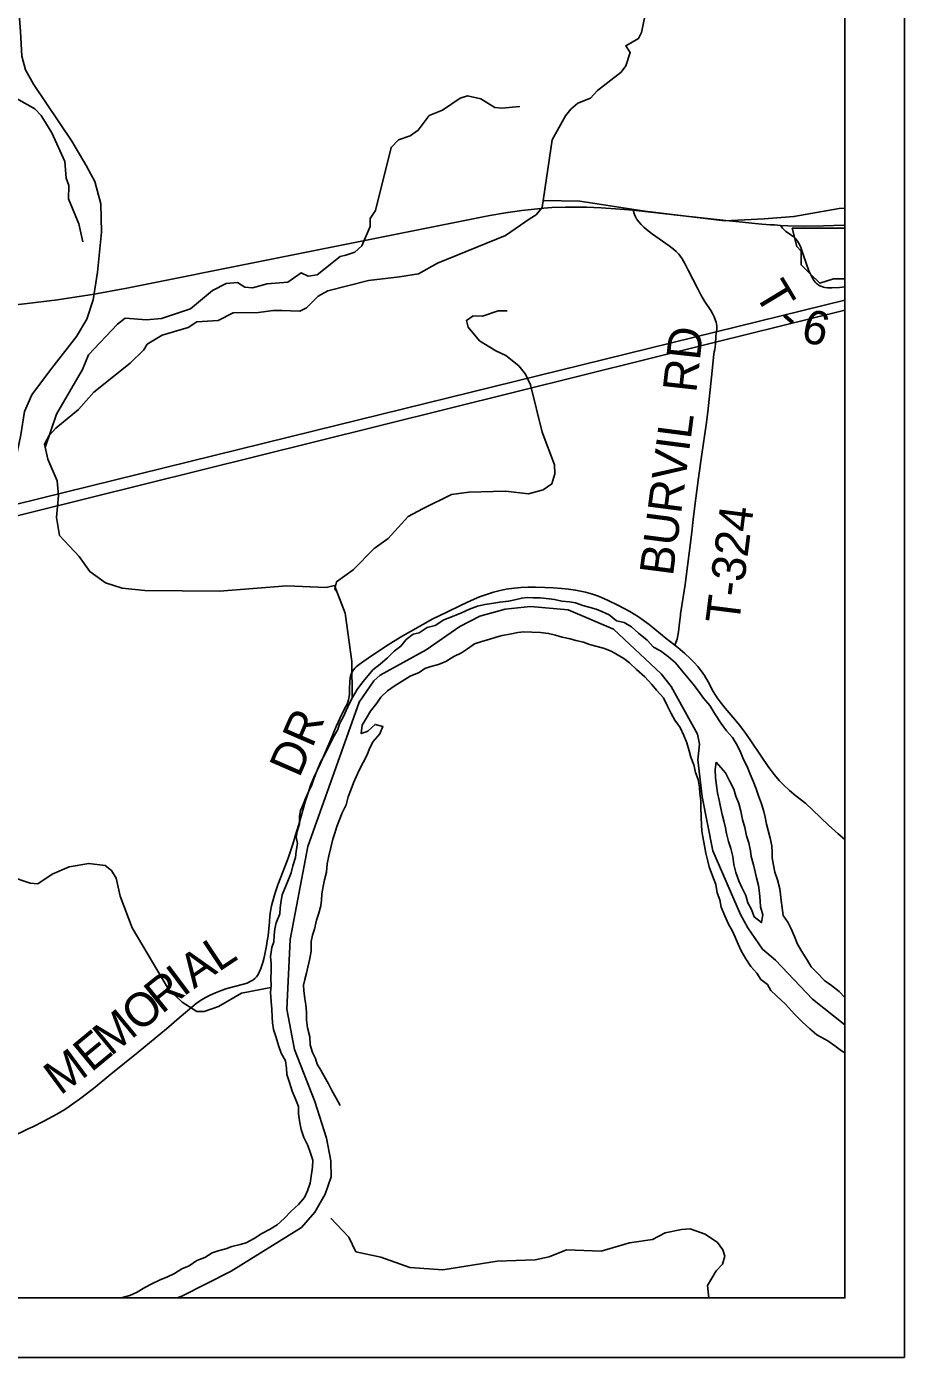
# Model space of a CAD drawing. Extents: x 0 to 34, y 0 to 22.
# Drawn here: x 7.523 to 9, y 14 to 16.238 of the extents above; entities that cross this region are included whole.
import ezdxf

# ---------------------------------------------------------------- set-up
doc = ezdxf.new("R2010")
doc.units = 0
for name, color, linetype in [('GM_X_Corporation', 7, 'Continuous'), ('GM_X_County_Road', 7, 'Continuous'), ('GM_X_County_Road_Text', 7, 'Continuous'), ('GM_X_Major_River', 7, 'Continuous'), ('GM_X_Minor_Lake', 7, 'Continuous'), ('GM_X_Minor_River', 7, 'Continuous'), ('GM_X_Rail_Line', 7, 'Continuous'), ('GM_X_State_Route', 7, 'Continuous'), ('GM_X_Township_Road', 7, 'Continuous'), ('GM_X_Township_Road_Text', 7, 'Continuous'), ('SH_Data', 7, 'Continuous')]:
    doc.layers.add(name, color=color, linetype=linetype)

msp = doc.modelspace()

# ---------------------------------------------------------------- linework, layer by layer
at = {"layer": 'GM_X_Corporation'}
for points in [[(2.1, 16.4477), (2.1, 14.1), (8.9, 14.1), (8.9, 16.2485)], [(7.4614, 14.1), (7.7766, 14.1), (7.7846, 14.103), (7.8675, 14.1449), (7.9856, 14.2182), (8.0084, 14.2441), (8.0256, 14.2746), (8.0359, 14.3039), (8.0349, 14.3304), (8.0278, 14.3687), (8.0084, 14.4303), (7.974, 14.5177), (7.9614, 14.5855), (7.9665, 14.7027), (7.9962, 14.8591), (8.083, 15.1017), (8.1073, 15.1379), (8.1182, 15.1474), (8.1953, 15.1901), (8.2521, 15.2295), (8.2856, 15.2464), (8.3286, 15.2585), (8.3709, 15.2629), (8.4345, 15.2573), (8.5104, 15.2245), (8.5908, 15.1499), (8.6079, 15.1281), (8.6517, 15.0484), (8.6556, 15.0313), (8.6528, 15.0048), (8.6598, 14.943), (8.6779, 14.8521), (8.7242, 14.7451), (8.7368, 14.7224), (8.7613, 14.6866), (8.783, 14.6678), (8.8452, 14.6022), (8.9, 14.5591), (8.9, 16.2485)]]:
    msp.add_lwpolyline(points, dxfattribs=at)
at = {"layer": 'GM_X_County_Road'}
for points in [[(7.6121, 14.4341), (7.6265, 14.4448), (7.6387, 14.4544), (7.6649, 14.4763), (7.7108, 14.5134), (7.7589, 14.5527), (7.7801, 14.5709), (7.8012, 14.5892), (7.8085, 14.595), (7.8161, 14.6003), (7.8241, 14.6051), (7.8324, 14.6094), (7.8409, 14.6132), (7.8495, 14.6166), (7.8584, 14.6196), (7.8733, 14.6239), (7.8884, 14.6276), (7.8943, 14.6295), (7.8971, 14.6308), (7.9008, 14.6326), (7.9039, 14.6345), (7.9073, 14.6371), (7.9101, 14.6399), (7.9129, 14.6441), (7.9147, 14.6477), (7.9175, 14.6543), (7.9193, 14.6593), (7.9209, 14.6643), (7.9229, 14.6724), (7.9268, 14.6923), (7.9283, 14.7008), (7.9297, 14.7091), (7.9317, 14.7325), (7.9328, 14.7426), (7.9339, 14.7507), (7.9355, 14.7596), (7.9399, 14.7755), (7.9425, 14.7844), (7.9461, 14.7947), (7.951, 14.8076), (7.9632, 14.8397), (7.9712, 14.8632), (7.9753, 14.8766), (7.9811, 14.8964), (7.9919, 14.9345), (7.997, 14.9496), (8.0009, 14.9619), (8.0077, 14.978), (8.0154, 14.9939), (8.0353, 15.0391), (8.0443, 15.061), (8.0503, 15.0746), (8.0583, 15.0908), (8.0625, 15.0985), (8.064, 15.1021), (8.0651, 15.1059), (8.0657, 15.1089), (8.0665, 15.115), (8.0667, 15.1181), (8.0668, 15.1242), (8.0673, 15.1367), (8.0678, 15.1428), (8.0684, 15.1459), (8.0693, 15.1489), (8.0705, 15.1517), (8.072, 15.1544), (8.0738, 15.1569), (8.0758, 15.1593), (8.078, 15.1614), (8.0828, 15.1654), (8.0905, 15.1707), (8.0981, 15.176), (8.1185, 15.1902), (8.1315, 15.1986), (8.1526, 15.2115), (8.2069, 15.2419), (8.2292, 15.2528), (8.2543, 15.2651), (8.2712, 15.2728), (8.2855, 15.2789), (8.2971, 15.2833), (8.3089, 15.2871), (8.3179, 15.2895), (8.3301, 15.292), (8.3393, 15.2933), (8.3547, 15.2949), (8.3671, 15.2955), (8.3795, 15.2955), (8.395, 15.2947), (8.4098, 15.2941), (8.4236, 15.2931), (8.4347, 15.2919), (8.4468, 15.2904), (8.4633, 15.2869), (8.4751, 15.2837), (8.4857, 15.2803), (8.5015, 15.2731), (8.5178, 15.265), (8.538, 15.2544), (8.5526, 15.2457), (8.5708, 15.2324), (8.5993, 15.2091), (8.6136, 15.1978)], [(8.6136, 15.1978), (8.6188, 15.1937), (8.6307, 15.1837), (8.6399, 15.1753), (8.6464, 15.1687), (8.6527, 15.1618), (8.6584, 15.1545), (8.6637, 15.1468), (8.6701, 15.1361), (8.6785, 15.1199), (8.682, 15.1136), (8.686, 15.1076), (8.6984, 15.0917), (8.7148, 15.0731), (8.7226, 15.0635), (8.7316, 15.0517), (8.7415, 15.0369), (8.7577, 15.0127), (8.772, 14.9922), (8.7814, 14.9797), (8.7896, 14.9703), (8.7961, 14.9636), (8.8068, 14.9535), (8.8174, 14.9446), (8.834, 14.9315), (8.8455, 14.9211), (8.8724, 14.8953), (8.8884, 14.8806), (8.9, 14.8708)], [(7.5326, 14.3874), (7.5522, 14.3973), (7.5741, 14.4091), (7.5874, 14.417), (7.5952, 14.422), (7.6027, 14.4275), (7.6121, 14.4341)], [(7.4965, 14.3697), (7.5273, 14.3847), (7.5326, 14.3874)]]:
    msp.add_lwpolyline(points, dxfattribs=at)
at = {"layer": 'GM_X_Major_River'}
for points in [[(8.5529, 15.2183), (8.541, 15.2287), (8.5288, 15.2358), (8.5155, 15.239), (8.5036, 15.2491), (8.491, 15.2546), (8.4815, 15.2582), (8.4713, 15.2611), (8.4591, 15.2644), (8.4469, 15.2691), (8.4367, 15.2705), (8.4238, 15.2718), (8.4116, 15.2747), (8.4022, 15.2757), (8.3881, 15.2774), (8.3756, 15.2776), (8.3662, 15.2782), (8.3563, 15.277), (8.3446, 15.2741), (8.3341, 15.2717), (8.3193, 15.2704), (8.3091, 15.2687), (8.294, 15.2662), (8.2816, 15.2634), (8.2684, 15.2583), (8.2552, 15.252), (8.2398, 15.2458), (8.2251, 15.2402), (8.2109, 15.2309), (8.1973, 15.2273), (8.1838, 15.2188), (8.1736, 15.2164), (8.1616, 15.2071), (8.1531, 15.196), (8.1415, 15.1875), (8.1303, 15.1767), (8.1179, 15.166), (8.106, 15.1563), (8.0981, 15.1467), (8.0892, 15.1364), (8.0792, 15.1233), (8.0718, 15.11), (8.0663, 15.1004), (8.0608, 15.0878), (8.0564, 15.0779), (8.0497, 15.0657), (8.0468, 15.0562), (8.0409, 15.0455), (8.0347, 15.0336), (8.0251, 15.0138), (8.0177, 15.0012), (8.0126, 14.9886), (8.0064, 14.9733), (8.0031, 14.9627), (7.9976, 14.9509), (7.9925, 14.9402), (7.9885, 14.9299), (7.9844, 14.92), (7.9823, 14.9105), (7.9825, 14.8976), (7.9785, 14.8846), (7.9771, 14.8751), (7.9788, 14.8645), (7.9767, 14.8516), (7.9757, 14.8406), (7.9714, 14.8265), (7.9682, 14.8147), (7.9641, 14.8037), (7.9601, 14.7941), (7.9535, 14.7781), (7.9511, 14.7652), (7.9501, 14.7557), (7.9491, 14.7458), (7.9432, 14.731), (7.9411, 14.7207), (7.9398, 14.7101), (7.9395, 14.6987), (7.9359, 14.6892), (7.9334, 14.6744), (7.9348, 14.6622), (7.935, 14.649), (7.934, 14.6376), (7.9345, 14.6247), (7.9339, 14.6145), (7.9349, 14.5982), (7.9359, 14.5857), (7.9364, 14.5724), (7.9369, 14.5626), (7.9386, 14.5516), (7.9434, 14.538), (7.947, 14.5248), (7.9517, 14.5116), (7.9591, 14.4988), (7.9604, 14.4863), (7.9613, 14.4757), (7.9656, 14.4621), (7.97, 14.4478), (7.9751, 14.4357), (7.9806, 14.4222), (7.9808, 14.4096), (7.9829, 14.3945)], [(8.098, 15.0538), (8.0961, 15.0527), (8.0863, 15.0491), (8.0876, 15.0632), (8.0946, 15.0747), (8.102, 15.0869), (8.1124, 15.1003), (8.1191, 15.1103), (8.1303, 15.121), (8.1419, 15.1291), (8.1551, 15.1373), (8.1686, 15.1458), (8.1836, 15.1517), (8.1934, 15.1587), (8.2032, 15.1622), (8.2164, 15.1654), (8.2288, 15.1705), (8.2419, 15.1787), (8.2551, 15.1849), (8.2648, 15.1919), (8.2768, 15.2), (8.2893, 15.204), (8.3028, 15.208), (8.313, 15.2115), (8.3232, 15.2143), (8.336, 15.2164), (8.35, 15.2192), (8.3598, 15.2201), (8.3734, 15.2196), (8.3878, 15.219), (8.4015, 15.2177), (8.4133, 15.2144), (8.4243, 15.2112), (8.4376, 15.2083), (8.4475, 15.2058), (8.46, 15.203), (8.4703, 15.1989), (8.4832, 15.1957), (8.4953, 15.1925), (8.5079, 15.1873), (8.5278, 15.1755), (8.5373, 15.168), (8.5496, 15.1568), (8.5634, 15.1445), (8.5753, 15.1318), (8.583, 15.122), (8.595, 15.1093), (8.6012, 15.0965), (8.6078, 15.083), (8.614, 15.0717), (8.6229, 15.0593), (8.6288, 15.0461), (8.6343, 15.0333), (8.6379, 15.0201), (8.6407, 15.0095), (8.6458, 14.9967), (8.6486, 14.9838), (8.6533, 14.9718), (8.6554, 14.9585), (8.6559, 14.9491), (8.6573, 14.9362), (8.6574, 14.9252), (8.658, 14.9093), (8.6586, 14.8953), (8.6591, 14.8858), (8.6608, 14.8756), (8.664, 14.8601), (8.6661, 14.848), (8.6693, 14.8348), (8.6717, 14.8249), (8.6772, 14.8098), (8.6827, 14.7955), (8.6848, 14.7811), (8.6895, 14.7698), (8.6916, 14.7574), (8.6979, 14.7427), (8.7041, 14.7287), (8.7111, 14.7171), (8.7154, 14.7069), (8.7205, 14.6948), (8.7256, 14.6839), (8.733, 14.6704), (8.7419, 14.6572), (8.7519, 14.6464), (8.7585, 14.6358), (8.7696, 14.6273), (8.7754, 14.6171), (8.785, 14.6082), (8.8, 14.594), (8.8153, 14.5771), (8.828, 14.5644), (8.8407, 14.5525), (8.8526, 14.5424), (8.8713, 14.5324), (8.8831, 14.5242), (8.8942, 14.5157), (8.9, 14.5123)], [(8.9, 14.6052), (8.8905, 14.6153), (8.8775, 14.6254), (8.8664, 14.6332), (8.8526, 14.6474), (8.8433, 14.6571), (8.8371, 14.6677), (8.829, 14.68), (8.8201, 14.6947), (8.815, 14.7079), (8.8091, 14.7218), (8.804, 14.732), (8.7963, 14.7433), (8.7942, 14.7561), (8.7925, 14.7686), (8.7916, 14.7785), (8.7904, 14.7883), (8.7867, 14.803), (8.782, 14.8159), (8.7799, 14.8276), (8.7775, 14.8404), (8.7774, 14.8499), (8.7768, 14.8605), (8.774, 14.8734), (8.7708, 14.8862), (8.768, 14.8968), (8.7659, 14.9085), (8.7635, 14.9183), (8.7595, 14.9312), (8.7544, 14.9444), (8.7508, 14.9561), (8.7457, 14.9689), (8.7403, 14.9809), (8.7355, 14.9938), (8.7293, 15.0058), (8.7246, 15.0167), (8.7188, 15.0295), (8.7106, 15.0423), (8.7006, 15.0536), (8.6917, 15.0663), (8.6813, 15.0821), (8.6727, 15.0964), (8.662, 15.1087), (8.6539, 15.1204), (8.6446, 15.1324), (8.6334, 15.1455), (8.6253, 15.156), (8.6149, 15.168), (8.6031, 15.178), (8.59, 15.1881), (8.5782, 15.1944), (8.5671, 15.2064), (8.5529, 15.2183)], [(8.0506, 14.4235), (8.0444, 14.4359), (8.0366, 14.4491), (8.0315, 14.46), (8.0242, 14.4728), (8.0183, 14.483), (8.0121, 14.4931), (8.0094, 14.5029), (8.0043, 14.5127), (8.0003, 14.5259), (7.9997, 14.5392), (7.9957, 14.5543), (7.9944, 14.5675), (7.9942, 14.5804), (7.9929, 14.5929), (7.9916, 14.6031), (7.9895, 14.6168), (7.9894, 14.6262), (7.9912, 14.6357), (7.994, 14.646), (7.9965, 14.6563), (7.9997, 14.6707), (8.0018, 14.6833), (8.002, 14.6996), (8.0041, 14.7102), (8.0074, 14.7201), (8.0113, 14.7353), (8.0142, 14.7452), (8.0182, 14.7593), (8.0195, 14.7688), (8.0201, 14.7798), (8.0222, 14.792), (8.0243, 14.803), (8.0279, 14.8163), (8.0289, 14.83), (8.0317, 14.8437), (8.0349, 14.8577), (8.0385, 14.8718), (8.0418, 14.8817), (8.0454, 14.8928), (8.0541, 14.9156), (8.0608, 14.9294), (8.0644, 14.9427), (8.0695, 14.9556), (8.0731, 14.9663), (8.0779, 14.9766), (8.083, 14.9877), (8.0896, 15.0007), (8.0955, 15.0125), (8.1007, 15.0251), (8.1062, 15.0358), (8.1173, 15.0488), (8.1228, 15.061), (8.1095, 15.0646), (8.098, 15.0538)], [(8.6836, 15.001), (8.6815, 14.9885), (8.6821, 14.9748), (8.6838, 14.962), (8.6855, 14.9495), (8.6883, 14.9374), (8.6907, 14.9257), (8.6936, 14.9128), (8.696, 14.9026), (8.6992, 14.8909), (8.7008, 14.8811), (8.704, 14.8675), (8.708, 14.8558), (8.7116, 14.8426), (8.7133, 14.8289), (8.7165, 14.8157), (8.7213, 14.8017), (8.7267, 14.7901), (8.7334, 14.7769), (8.7369, 14.7644), (8.7428, 14.7531), (8.7475, 14.7407), (8.7594, 14.7314), (8.7615, 14.7417)], [(8.7615, 14.7417), (8.7618, 14.7443), (8.7582, 14.7575), (8.7573, 14.7678), (8.756, 14.781), (8.7543, 14.7935), (8.7511, 14.8063), (8.7487, 14.8165), (8.7459, 14.8286), (8.7423, 14.8422), (8.7414, 14.8521), (8.7381, 14.8653), (8.7346, 14.8774), (8.7317, 14.8914), (8.7274, 14.9046), (8.7249, 14.9189), (8.7217, 14.9314), (8.7166, 14.9438), (8.713, 14.9559), (8.706, 14.9698), (8.699, 14.983), (8.6836, 15.001)], [(7.9829, 14.3945), (7.9853, 14.3832), (7.9897, 14.37), (7.9967, 14.3564), (8.0006, 14.3451), (8.0046, 14.3319), (8.0044, 14.3198), (8.0002, 14.2932), (7.9959, 14.2802), (7.9908, 14.2688), (7.9807, 14.2573), (7.9687, 14.2461), (7.9568, 14.2334), (7.9449, 14.223), (7.9317, 14.2149), (7.9193, 14.2082), (7.9062, 14.1997), (7.893, 14.1927), (7.8825, 14.1899), (7.8685, 14.1863), (7.8587, 14.1828), (7.8455, 14.1792), (7.8358, 14.1756), (7.8234, 14.1682), (7.8098, 14.1627), (7.7971, 14.1542), (7.7843, 14.1487), (7.7723, 14.141), (7.7606, 14.1355), (7.7482, 14.1304), (7.7343, 14.1238), (7.7223, 14.1175), (7.7095, 14.1098), (7.6971, 14.1039), (7.6862, 14.1011), (7.6828, 14.1)]]:
    msp.add_lwpolyline(points, dxfattribs=at)
at = {"layer": 'GM_X_Minor_Lake'}
for points in [[(8.8111, 15.8992), (8.8188, 15.8683), (8.8266, 15.8606), (8.8266, 15.8374), (8.842, 15.8219), (8.8575, 15.8064), (8.8807, 15.8142), (8.8961, 15.8142), (8.9, 15.8142)], [(8.9, 15.8992), (8.873, 15.8992), (8.8111, 15.8992)]]:
    msp.add_lwpolyline(points, dxfattribs=at)
at = {"layer": 'GM_X_Minor_River'}
for points in [[(7.5143, 16.286), (7.5155, 16.2768), (7.5069, 16.2654), (7.4929, 16.2615), (7.4805, 16.2539), (7.4497, 16.2244), (7.4371, 16.1929), (7.4374, 16.1682), (7.4446, 16.1573), (7.4671, 16.1392), (7.537, 16.0999), (7.548, 16.0886), (7.5657, 16.0595), (7.5876, 16.0115), (7.5901, 15.9831), (7.5944, 15.971), (7.5938, 15.9486), (7.6112, 15.9063), (7.6182, 15.876)], [(8.0712, 15.109), (8.0706, 15.1704), (8.059, 15.2514), (8.0412, 15.298), (8.0272, 15.2948), (7.961, 15.2978), (7.8477, 15.2887), (7.7221, 15.2897), (7.6843, 15.2936), (7.6559, 15.3029), (7.6296, 15.3217), (7.6116, 15.3469), (7.5788, 15.3824), (7.5737, 15.4123), (7.5771, 15.4498), (7.5747, 15.4741), (7.5592, 15.5108), (7.5534, 15.5358), (7.5612, 15.5506), (7.5724, 15.5628), (7.6104, 15.5942), (7.6366, 15.6232), (7.6978, 15.6721), (7.7203, 15.6943), (7.7263, 15.7038), (7.7515, 15.7192), (7.7952, 15.732), (7.8099, 15.7419), (7.8458, 15.7441), (7.871, 15.7568), (7.9134, 15.7571), (7.9379, 15.7606), (7.9527, 15.7607), (7.9829, 15.7594), (7.9942, 15.7652), (8.0141, 15.7847), (8.0299, 15.7935), (8.0986, 15.8114), (8.1507, 15.8175), (8.1828, 15.8226), (8.2144, 15.8403), (8.3289, 15.8866), (8.3707, 15.9153), (8.3805, 15.9214), (8.3906, 15.934), (8.4074, 16.0475), (8.4301, 16.0879), (8.4387, 16.0993), (8.4504, 16.1092), (8.4718, 16.1177), (8.4838, 16.1307), (8.5233, 16.1617), (8.5315, 16.1724), (8.5389, 16.1944), (8.5312, 16.2061), (8.5527, 16.2184), (8.5575, 16.2283), (8.5638, 16.2581)], [(7.5546, 15.5305), (7.5737, 15.5863), (7.6174, 15.6613), (7.6277, 15.6864), (7.6761, 15.7376), (7.6892, 15.7479), (7.7252, 15.7451), (7.7501, 15.7472), (7.7991, 15.7635), (7.8359, 15.7941), (7.8593, 15.806), (7.8782, 15.8076), (7.8907, 15.7997), (7.9032, 15.7987), (7.9281, 15.8053), (7.9629, 15.8082), (7.9854, 15.8243), (7.9968, 15.8183), (8.0119, 15.8207), (8.0506, 15.8513), (8.0604, 15.8536), (8.0755, 15.8587), (8.0871, 15.8694), (8.1012, 15.9021), (8.1011, 15.9153), (8.1101, 15.9287), (8.1364, 16.035), (8.1488, 16.0476), (8.1688, 16.0542), (8.1823, 16.0638), (8.2006, 16.0886), (8.2232, 16.0978), (8.2525, 16.1177), (8.265, 16.1216), (8.2873, 16.1165), (8.3113, 16.1022), (8.3226, 16.1008), (8.3532, 16.104)], [(8.3923, 15.9455), (8.454, 15.9447), (8.5634, 15.9276), (8.6978, 15.9115), (8.7643, 15.915), (8.8141, 15.9187), (8.8904, 15.9322), (8.9, 15.9328)], [(8.0446, 15.2889), (8.0416, 15.2926), (8.0449, 15.3044), (8.0727, 15.3247), (8.108, 15.3602), (8.1316, 15.3771), (8.165, 15.4141), (8.1891, 15.4272), (8.238, 15.4514), (8.2675, 15.4554), (8.3291, 15.4569), (8.3677, 15.4523), (8.3926, 15.4593), (8.4069, 15.4692), (8.412, 15.486), (8.4112, 15.5011), (8.3907, 15.556), (8.3711, 15.6358), (8.3626, 15.6536), (8.3512, 15.6676), (8.3295, 15.6848), (8.3128, 15.6931), (8.285, 15.7099), (8.2659, 15.7329), (8.2632, 15.7439), (8.2745, 15.7516), (8.2904, 15.7513), (8.3168, 15.7602), (8.3319, 15.7599)], [(7.9344, 14.622), (7.885, 14.6124), (7.8459, 14.5901), (7.8221, 14.5816), (7.8097, 14.5815), (7.7853, 14.5973), (7.7621, 14.6191), (7.7011, 14.7222), (7.681, 14.7759), (7.6743, 14.8059), (7.6663, 14.8187), (7.6553, 14.8273), (7.628, 14.8309), (7.5952, 14.825), (7.5662, 14.8127), (7.5425, 14.7962), (7.5292, 14.7973), (7.4961, 14.8089)], [(8.0353, 14.2341), (8.0657, 14.2022), (8.0773, 14.1776), (8.1193, 14.1688), (8.1683, 14.1513), (8.2235, 14.1475), (8.3152, 14.1618), (8.3787, 14.1638), (8.4025, 14.1693), (8.4315, 14.1808), (8.4898, 14.1786), (8.5373, 14.1929), (8.5762, 14.1985), (8.5973, 14.2097), (8.6252, 14.2152), (8.6396, 14.216), (8.665, 14.2071), (8.6855, 14.1932), (8.6947, 14.1811), (8.6978, 14.1705), (8.6938, 14.1565), (8.6836, 14.1458), (8.6687, 14.121), (8.6712, 14.1)]]:
    msp.add_lwpolyline(points, dxfattribs=at)
at = {"layer": 'GM_X_Rail_Line'}
for points in [[(7.3608, 15.4019), (7.4193, 15.4215), (7.4527, 15.4405), (7.4789, 15.4634), (7.4972, 15.4929), (7.5077, 15.5217), (7.5136, 15.5518), (7.5201, 15.5911), (7.5319, 15.6186), (7.562, 15.6585), (7.6072, 15.7168), (7.6249, 15.7462), (7.6353, 15.7789), (7.6425, 15.8254), (7.6491, 15.8922), (7.6484, 15.94), (7.638, 15.9779), (7.6236, 16.0048), (7.5994, 16.0454), (7.5352, 16.1416), (7.5215, 16.1652), (7.5156, 16.1887), (7.513, 16.23), (7.5097, 16.2732)], [(4.7232, 14.7487), (4.8596, 14.7823), (5.0004, 14.8171), (5.0735, 14.8354), (5.1763, 14.8606), (5.27, 14.8838), (5.3976, 14.9152), (5.5295, 14.9475), (5.6419, 14.9754), (5.7924, 15.0128), (5.9194, 15.0442), (6.0332, 15.0721), (6.178, 15.108), (6.2632, 15.1289), (6.9157, 15.2894), (7.2078, 15.3612), (7.3771, 15.4031), (8.007, 15.5582), (8.6833, 15.725), (8.9, 15.7782)], [(7.1524, 15.3272), (8.006, 15.5393), (8.6824, 15.7072), (8.9, 15.7613)]]:
    msp.add_lwpolyline(points, dxfattribs=at)
at = {"layer": 'GM_X_State_Route'}
for points in [[(7.4176, 15.7609), (7.5201, 15.7717), (7.5756, 15.7788), (7.637, 15.7883), (7.692, 15.7985), (7.9267, 15.8452), (8.0334, 15.8665), (8.2801, 15.9162), (8.3025, 15.9204), (8.329, 15.9252), (8.3566, 15.929), (8.3937, 15.9328), (8.4072, 15.9338), (8.4297, 15.9345), (8.4416, 15.9347), (8.465, 15.9344), (8.4898, 15.9336), (8.522, 15.9311)], [(8.522, 15.9311), (8.544, 15.9293), (8.5487, 15.929), (8.6227, 15.9206), (8.6999, 15.9119), (8.7274, 15.9091), (8.7435, 15.9073), (8.7602, 15.9061), (8.7748, 15.905), (8.7817, 15.9045)], [(8.7817, 15.9045), (8.7916, 15.9037), (8.8041, 15.9032), (8.8301, 15.9025), (8.8642, 15.9029), (8.8984, 15.904), (8.9, 15.9041)]]:
    msp.add_lwpolyline(points, dxfattribs=at)
at = {"layer": 'GM_X_Township_Road'}
for points in [[(8.6136, 15.1978), (8.6155, 15.2022), (8.6167, 15.205), (8.6176, 15.208), (8.6191, 15.214), (8.62, 15.2201), (8.6216, 15.2355), (8.6233, 15.2478), (8.6235, 15.2509), (8.6239, 15.254), (8.6311, 15.3001), (8.6353, 15.3309), (8.638, 15.3525), (8.6416, 15.3834), (8.6452, 15.4143), (8.649, 15.4452), (8.6534, 15.4792), (8.6593, 15.5192), (8.6664, 15.5685), (8.6692, 15.5901), (8.6714, 15.6117), (8.673, 15.6272), (8.6757, 15.6488), (8.6794, 15.6871), (8.68, 15.691), (8.681, 15.6951), (8.6824, 15.7042), (8.6825, 15.7073), (8.6827, 15.7136), (8.6829, 15.7167), (8.6836, 15.7228), (8.6841, 15.7259), (8.6845, 15.7289), (8.6843, 15.7351), (8.6839, 15.7381), (8.6832, 15.7411), (8.6823, 15.7441), (8.68, 15.7499), (8.6772, 15.7555), (8.6742, 15.7609), (8.664, 15.7765), (8.6576, 15.7872), (8.6518, 15.7982), (8.6364, 15.8288), (8.6306, 15.8397), (8.6259, 15.8478), (8.6224, 15.853), (8.6204, 15.8554), (8.6162, 15.8598), (8.6115, 15.864), (8.6042, 15.8697), (8.5761, 15.8893), (8.5662, 15.8968), (8.5615, 15.9009), (8.557, 15.9053), (8.553, 15.91), (8.5494, 15.915), (8.5474, 15.9184), (8.5459, 15.9221), (8.544, 15.9293)], [(8.7916, 15.9037), (8.795, 15.8992), (8.7978, 15.8962), (8.8008, 15.8937), (8.8053, 15.8906), (8.8092, 15.8882), (8.8143, 15.8843), (8.8165, 15.8821), (8.8185, 15.8797), (8.8203, 15.8772), (8.8235, 15.8719), (8.8258, 15.8665), (8.8302, 15.8534), (8.8392, 15.8276), (8.8429, 15.8193), (8.8452, 15.8152), (8.8485, 15.8104), (8.8501, 15.8086), (8.8518, 15.8066), (8.8543, 15.8046), (8.8558, 15.8033), (8.858, 15.802), (8.861, 15.8009), (8.8637, 15.8002), (8.8663, 15.7996), (8.8711, 15.7988), (8.8782, 15.7986), (8.8909, 15.7994), (8.9, 15.8004)]]:
    msp.add_lwpolyline(points, dxfattribs=at)
at = {"layer": 'SH_Data'}
for p, q in [((9, 21), (9, 14)), ((8.9, 20.9), (8.9, 14.1)), ((2.1, 14.1), (8.9, 14.1)), ((2, 14), (9, 14))]:
    msp.add_line(p, q, dxfattribs=at)

# ---------------------------------------------------------------- texts
at = {"layer": 'GM_X_County_Road_Text'}
for s, height, rotation, p in [('DR', 0.05682, 66.5501, (7.982, 14.9733)), ('A', 0.0568, 34.5277, (7.805, 14.6191)), ('L', 0.0568, 33.6936, (7.846, 14.6473)), ('R', 0.0568, 38.8366, (7.7509, 14.5765)), ('I', 0.0568, 36.898, (7.7868, 14.6055)), ('O', 0.0568, 39.5593, (7.7125, 14.5448)), ('M', 0.0568, 39.5616, (7.665, 14.5055)), ('E', 0.0568, 39.5784, (7.6322, 14.4784)), ('M', 0.0568, 36.4493, (7.5799, 14.4397))]:
    msp.add_text(s, height=height, rotation=rotation, dxfattribs=at).set_placement(p)
at = {"layer": 'GM_X_Township_Road_Text'}
for s, height, rotation, p in [('T', 0.0568, 301.1159, (8.7466, 15.7895)), ('6', 0.0568, 345.4565, (8.8237, 15.7099)), ('-', 0.0568, 319.2851, (8.7812, 15.7381)), ('RD', 0.05682, 83.6616, (8.6498, 15.6212)), ('BURVIL', 0.05682, 82.6022, (8.6106, 15.3128)), ('T-324', 0.05682, 82.7383, (8.7216, 15.2314))]:
    msp.add_text(s, height=height, rotation=rotation, dxfattribs=at).set_placement(p)

doc.saveas('drawing.dxf')
